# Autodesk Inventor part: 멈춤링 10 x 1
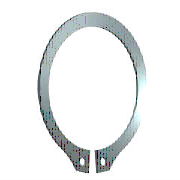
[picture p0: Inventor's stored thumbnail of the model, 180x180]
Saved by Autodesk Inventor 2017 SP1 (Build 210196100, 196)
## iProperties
IsCustomPart: 0
Created: 2021-07
Part Number: 멈춤링 10 x 1
Material: 강철, 연강
Description: 리테이닝 링(C형)
Document SubType Name: Modeling
Standard: KS B 1336
Designer: mdu
Standards Organization: KS
Language: ko-KR
Size Designation: 10 x 1
Categories: <MemberInstance><Categories><Category DisplayName="샤프트 부품" InternalName="7f7aeb1f-a693-4053-b835-cee3144e0d98" Mnemonic="SHFT"><Category DisplayName="써클립" Inter
Density: 7.86 g/cm^3
Mass: 0.423084 g
Surface Area: 1.9243 cm^2
Volume: 0.0538275 cm^3
Appearance: 파란색 - 벽 페인트 - 광택
Author: mdu
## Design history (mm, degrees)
sketch "스케치1"
  geometry: L1 (-6, 0)-(6, 0) reference; L2 (0, 20.189)-(0, -80.536) reference; L3 (-48.09, 0)-(48.09, 0) reference; L4 (-0.3, -9.791)-(-0.3, -12.791); L5 (-0.3, -6.54)-(-0.3, -13.29); L6 (-2.795, 1.6)-(3.672, 1.6); L7 (0.3, -6.54)-(0.3, -13.29); L8 (0.3, -9.791)-(0.3, -12.791); C1 r 0.6 at (-1.2, -11.486); C2 r 0.6 at (1.2, -11.486); A1 r 4.8 centre (0, -5) between (0.3, -9.791) and (-0.3, -9.791); A2 r 6.2 centre (0, -4.6) between (2.988, -10.033) and (-2.988, -10.033); A3 r 7.796 centre (0, -5) between (-1.418, -12.666) and (-0.3, -12.791); A4 r 1.2 centre (-1.2, -11.486) between (-2.383, -11.285) and (-1.418, -12.666); A5 r 1.2 centre (-3.566, -11.084) between (-2.383, -11.285) and (-2.988, -10.033); A6 r 1.2 centre (3.566, -11.084) between (2.988, -10.033) and (2.383, -11.285); A7 r 1.2 centre (1.2, -11.486) between (1.418, -12.666) and (2.383, -11.285); A8 r 7.796 centre (0, -5) between (0.3, -12.791) and (1.418, -12.666)
  constraints: 16 point on circle, 12 end point, 10 centre point, 9 symmetric about line, 5 point on line, 4 tangent, 3 coincident, 2 horizontal, 1 perpendicular, 1 vertical, 5 other
  dimensions: "d0" = 9.6 diameter of A1 (= ND); "d1" = 3 distance of L4.end L4.start (= SRB2); "d6" = 0.3 distance between parallel lines of L2 L5 (= 0.25 x SD5); "d7" = 1.6 distance between parallel lines of L6 L3 (= SRB1); "d8" = 0.4 distance of A1.centre A2.centre (= 0.25 x SRB1); "d9" = 1.2 radius of A4 (= SD5); "d10" = 1.2 radius of A5 (= SD5); "d11" = 0.9 distance from line of L4 A4.centre (= 0.75 x SD5); "d12" = 1.2 diameter of C1 (= SD5); "d13" = 1.2 diameter of C2 (= SD5); "d14" = 5 distance from line of A1.centre L1 (= 0.5 x WD)
extrude "본체" new body sketch "스케치1" distance "d2" = 1 (= SD); taper "d3" = 0 deg
workaxis "Work Axis1"
workplane "Work Plane1"
body "Solid1"
other parameters: "SD" = 1 [user parameter; used in 1 equation term], "SRB1" = 1.6 [user parameter; used in 2 equation terms], "ND" = 9.6 [user parameter; used in 1 equation term], "SRB2" = 3 [user parameter; used in 1 equation term], "SD5" = 1.2 [user parameter; used in 6 equation terms], "d15" = 0, "d16" = 0, "d17" = 0, "d41" = 0, "d42" = 0, "SD3" = 9.3 [user parameter], "WDMAX" = 11 [user parameter]
